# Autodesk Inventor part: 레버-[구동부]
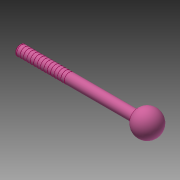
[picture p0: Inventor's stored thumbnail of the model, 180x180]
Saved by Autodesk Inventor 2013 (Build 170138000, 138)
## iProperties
Created: 2015-12
Part Number: 레버-[구동부]
Material: 스테인리스강
Document SubType Name: Modeling
Designer: mduedu
Density: 8.08 g/cm^3
Mass: 29.6046 g
Surface Area: 20.4663 cm^2
Volume: 3.66393 cm^3
Author: mduedu
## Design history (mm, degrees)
sketch "스케치1"
  geometry: C1 r 3 at (0, 0); 1 further point
  constraints: 1 centre point, 1 coincident
  dimensions: "d0" = 6 diameter of C1
extrude "돌출1" new body sketch "스케치1" distance "d1" = 75; taper "d2" = 0 deg
sketch "스케치2"
  geometry: L1 (7.5, 0)-(-6, 0); L2 (-6, 4.5)-(-6, 0); A1 r 7.5 centre (0, 0) between (7.5, 0) and (-6, 4.5); 2 further points
  constraints: 4 end point, 2 coincident, 2 point on circle, 1 centre point, 1 horizontal, 1 perpendicular, 1 point on line
  dimensions: "d3" = 15 diameter of A1; "d10" = 6 distance from line of L2 point (0, 0)
revolve "회전1" sketch "스케치2" stored, may be unused: angle "d4" = 90 deg
chamfer "모따기1" distance "d7" = 0.5; stored, may be unused: second distance "d8" = 2, angle "d9" = 45 deg
fillet "모깎기2" dims "d11" = 0.3
sketch "스케치4"
  geometry: L1 (-75, -2.5)-(-75, 2.5) reference; L2 (-75, 0)-(0, 0); L3 (-6.3, 3)-(-74.5, 3) reference; L4 (-74, 3)-(-73.9, 3); L5 (-73.9, 3)-(-73.9, 2.9); L6 (-73.9, 2.9)-(-74, 2.9); L7 (-74, 2.9)-(-74, 3)
  constraints: 10 end point, 2 parallel, 2 perpendicular, 1 horizontal, 1 midpoint, 1 point on line
  dimensions: "d17" = 1 distance between parallel lines of L7 L1; "d18" = 0.1 distance of L5.end L6.end; "d19" = 0.1 distance of L4.end L5.end
revolve "회전3" sketch "스케치4" stored, may be unused: angle "d20" = 90 deg
node "솔리드1"
pattern_linear "직사각형 패턴1" dims "d23" = 2
